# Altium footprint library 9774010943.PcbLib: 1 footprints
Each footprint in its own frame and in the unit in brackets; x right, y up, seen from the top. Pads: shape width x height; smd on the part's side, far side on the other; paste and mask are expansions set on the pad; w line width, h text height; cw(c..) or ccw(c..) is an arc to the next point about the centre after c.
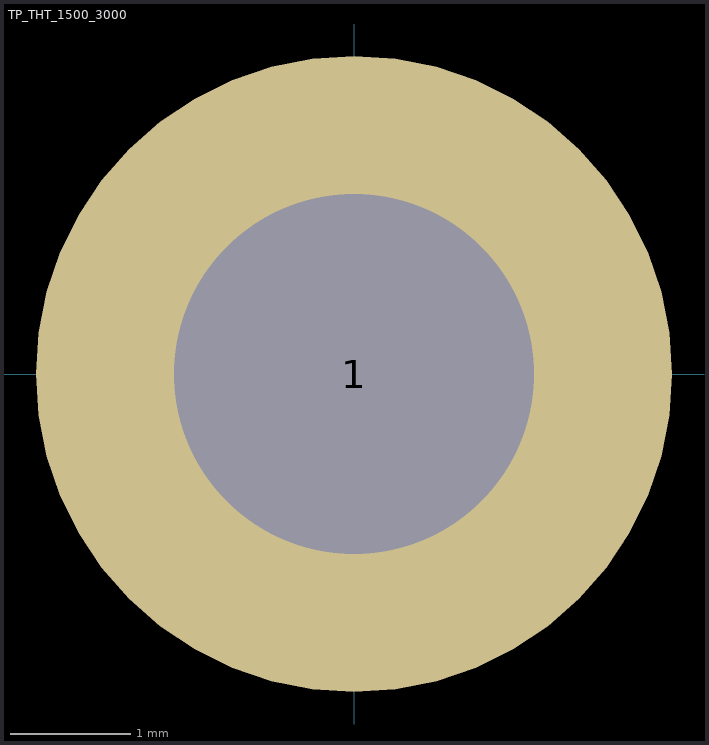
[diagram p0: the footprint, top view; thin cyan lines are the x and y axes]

## TP_THT_1500_3000 [mm]
pads (1):
  round 5.3 / inner round 3.6 / far side round 5.3 hole 3: 1(0,0)
Top Paste:
  circle w1: c0,0 r2.05
Mechanical 13:
  circle w0.102: c0,0 r1.5
3D body "9774010943 (rev1).stp": height 1.01, standoff -1.39, extent -2.175,-2.172 2.175,2.172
